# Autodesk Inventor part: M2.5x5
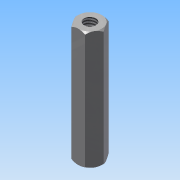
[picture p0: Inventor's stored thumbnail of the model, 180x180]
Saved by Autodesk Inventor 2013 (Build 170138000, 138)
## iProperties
Created: 2012-08
Part Number: M2.5x5
Material: Stahl
Document SubType Name: Modeling
Designer: rYan
Density: 7.85 g/cm^3
Mass: 1.6739 g
Surface Area: 4.23084 cm^2
Volume: 0.213236 cm^3
Author: rYan
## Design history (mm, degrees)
derived "Abstandsbolzen Typ A.ipt"
feature "Volumenkörper1::Abstandsbolzen Typ A.ipt"
tag "Bezeichnung1"
node "Volumenkörper1"
other parameters: "SW" = 4, "d2" = 0, "d16" = 45 deg
